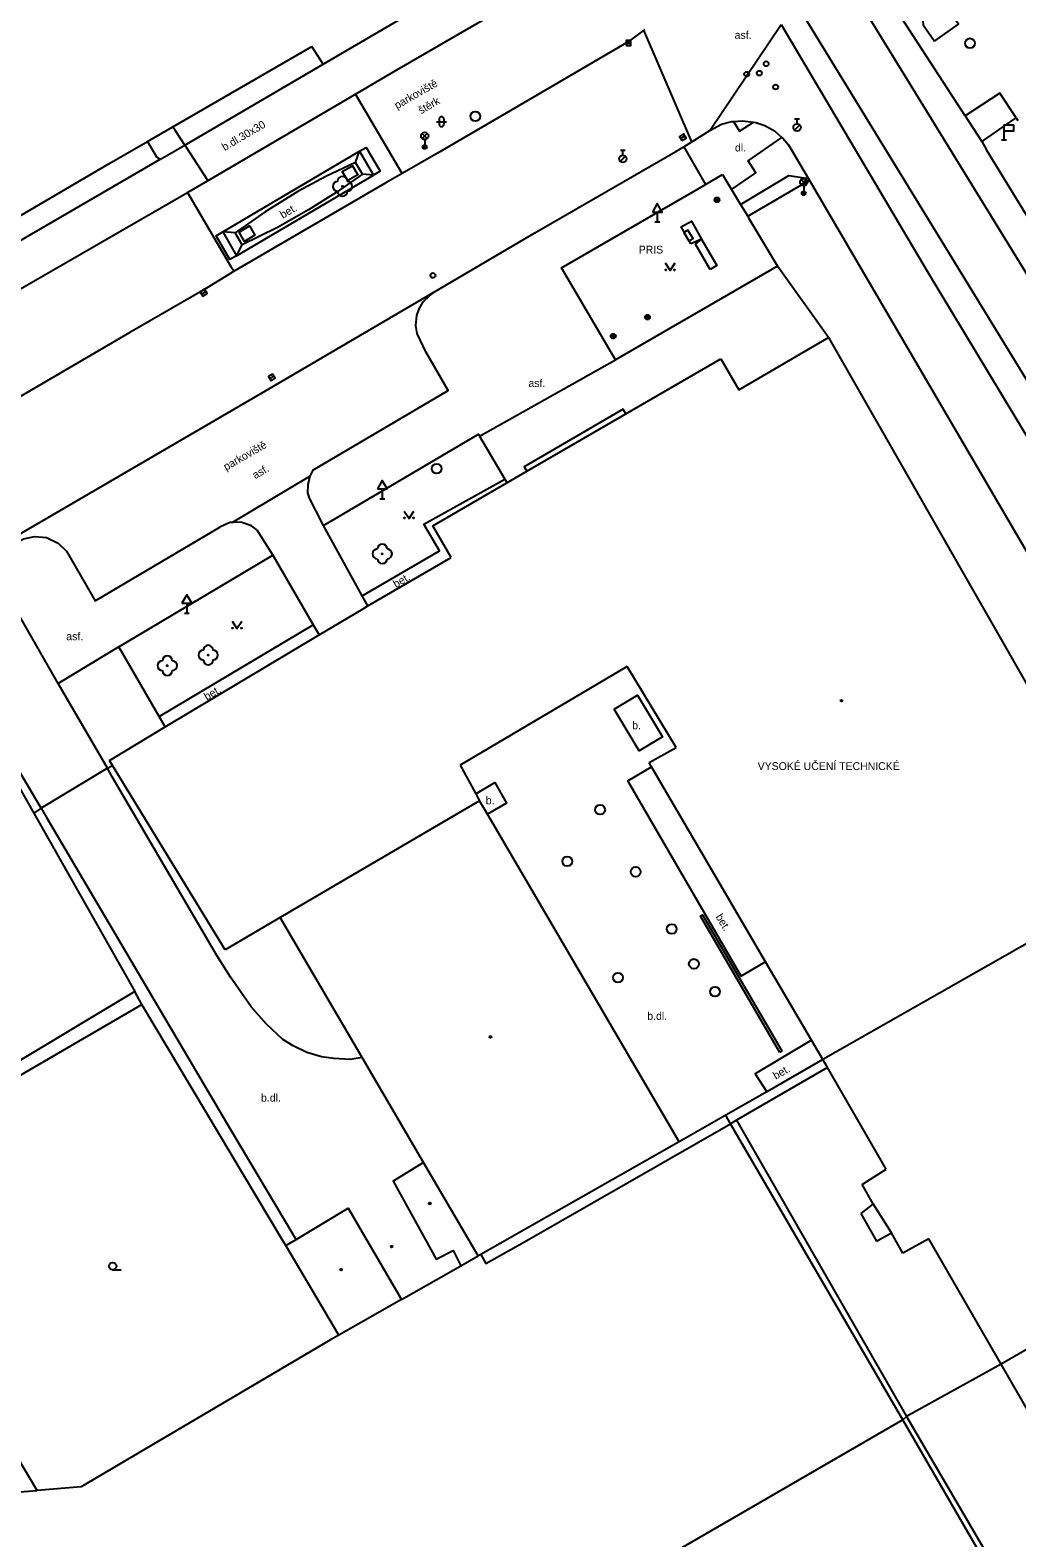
# Model space of a CAD drawing. Extents: x -599770 to -598493, y -1162076 to -1159209.
# Drawn here: x -599124.7 to -599074.3, y -1159515 to -1159438 of the extents above; entities that cross this region are included whole.
import ezdxf

# ---------------------------------------------------------------- set-up
doc = ezdxf.new("R2010")
doc.units = 0
doc.layers.add('Podklad', color=7, linetype='Continuous')

msp = doc.modelspace()

# ---------------------------------------------------------------- linework, layer by layer
at = {"layer": 'Podklad'}
for p, q in [((-599094.245, -1159438.68), (-599093.995, -1159438.68)), ((-599103.923, -1159442.698), (-599103.423, -1159442.698)), ((-599103.798, -1159442.573), (-599103.798, -1159442.823)), ((-599103.548, -1159442.573), (-599103.548, -1159442.823)), ((-599085.639, -1159443.126), (-599085.374, -1159442.861)), ((-599085.635, -1159442.552), (-599085.385, -1159442.552)), ((-599085.51, -1159442.802), (-599085.51, -1159442.552)), ((-599104.663, -1159443.56), (-599104.398, -1159443.295)), ((-599104.663, -1159443.295), (-599104.398, -1159443.56)), ((-599104.53, -1159443.615), (-599104.53, -1159443.99)), ((-599091.457, -1159443.555), (-599091.243, -1159443.425)), ((-599075.065, -1159443.62), (-599074.815, -1159443.62)), ((-599074.94, -1159443.17), (-599074.94, -1159443.62)), ((-599094.539, -1159444.726), (-599094.274, -1159444.461)), ((-599094.535, -1159444.152), (-599094.285, -1159444.152)), ((-599094.41, -1159444.402), (-599094.41, -1159444.152)), ((-599085.303, -1159445.92), (-599085.038, -1159445.655)), ((-599085.303, -1159445.655), (-599085.038, -1159445.92)), ((-599085.17, -1159445.975), (-599085.17, -1159446.35)), ((-599092.65, -1159447.311), (-599092.65, -1159447.82)), ((-599092.775, -1159447.82), (-599092.525, -1159447.82)), ((-599115.927, -1159451.495), (-599115.713, -1159451.365)), ((-599112.447, -1159455.825), (-599112.233, -1159455.695)), ((-599106.825, -1159461.96), (-599106.575, -1159461.96)), ((-599106.7, -1159461.451), (-599106.7, -1159461.96)), ((-599116.68, -1159467.291), (-599116.68, -1159467.8)), ((-599116.805, -1159467.8), (-599116.555, -1159467.8)), ((-599120.47, -1159501.337), (-599120.032, -1159501.337))]:
    msp.add_line(p, q, dxfattribs=at)
for points in [[(-599039.34, -1159506.49), (-599081.92, -1159437.24), (-599097.95, -1159410.38), (-599103.87, -1159400.3), (-599106.93, -1159394.94), (-599112.18, -1159386.13), (-599122.02, -1159369.06), (-599131.59, -1159352.73), (-599141.23, -1159336.24), (-599151.13, -1159319.11), (-599165.12, -1159295.05), (-599171.44, -1159284.11), (-599177.89, -1159272.64), (-599183.68, -1159262.09), (-599192.24, -1159246.86)], [(-599194.89, -1159248.28), (-599186.31, -1159263.55), (-599180.61, -1159273.94), (-599174.09, -1159285.5), (-599167.84, -1159296.37), (-599153.7, -1159320.73), (-599143.87, -1159337.58), (-599134.14, -1159354.17), (-599124.59, -1159370.66), (-599115.4, -1159386.56), (-599106.63, -1159401.44), (-599100.63, -1159411.8), (-599090.87, -1159427.91), (-599085.27, -1159437.13), (-599041.98, -1159507.82)], [(-599109.72, -1159439.76), (-599096.69, -1159432.14)], [(-599106.16, -1159440.17), (-599095.45, -1159433.96)], [(-599076.919, -1159442.396), (-599081.578, -1159435.231)], [(-599078.495, -1159438.582), (-599077.258, -1159437.72), (-599077.856, -1159436.898), (-599078.12, -1159436.786), (-599078.404, -1159436.756), (-599078.621, -1159436.774), (-599078.772, -1159436.84), (-599078.907, -1159436.966), (-599079.033, -1159437.172), (-599079.106, -1159437.406), (-599079.063, -1159437.75), (-599078.495, -1159438.582)], [(-599093.29, -1159437.99), (-599093.338, -1159438.026), (-599094.14, -1159438.62), (-599100.16, -1159442.14), (-599103.85, -1159444.29)], [(-599090.88, -1159443.73), (-599093.338, -1159438.026)], [(-599089.97, -1159443.15), (-599086.329, -1159437.731)], [(-599086.329, -1159437.731), (-599078.82, -1159450.42), (-599073.9, -1159458.57), (-599067.11, -1159469.527)], [(-599118.69, -1159443.71), (-599117.393, -1159442.96), (-599110.302, -1159438.861)], [(-599109.72, -1159439.76), (-599110.18, -1159439.05), (-599110.302, -1159438.861)], [(-599117.91, -1159444.55), (-599116.786, -1159443.892), (-599109.72, -1159439.76)], [(-599116.65, -1159446.31), (-599115.6, -1159445.7), (-599108.07, -1159441.29), (-599106.16, -1159440.17)], [(-599105.69, -1159445.35), (-599108.07, -1159441.29)], [(-599074.325, -1159442.504), (-599075.149, -1159441.239), (-599076.919, -1159442.396), (-599076.068, -1159443.706)], [(-599089.97, -1159443.15), (-599089.37, -1159442.83), (-599088.85, -1159442.69), (-599088.76, -1159442.68), (-599088.3, -1159442.65), (-599087.74, -1159442.72), (-599087.61, -1159442.74), (-599087.16, -1159442.9), (-599086.66, -1159443.17), (-599086.28, -1159443.5), (-599086.23, -1159443.54), (-599085.93, -1159443.89)], [(-599088.76, -1159442.68), (-599088.454, -1159443.179), (-599087.74, -1159442.72)], [(-599076.068, -1159443.706), (-599075.99, -1159443.652), (-599074.423, -1159442.572), (-599074.325, -1159442.504)], [(-599074.325, -1159442.504), (-599074.24, -1159442.63)], [(-599120.61, -1159444.82), (-599118.69, -1159443.71)], [(-599118.69, -1159443.71), (-599118.23, -1159444.5)], [(-599116.702, -1159444.021), (-599116.786, -1159443.892), (-599117.264, -1159443.158), (-599117.393, -1159442.96)], [(-599091.71, -1159444.22), (-599091.3, -1159443.98), (-599090.88, -1159443.73), (-599089.97, -1159443.15)], [(-599088.86, -1159446.16), (-599087.618, -1159445.318), (-599088.015, -1159444.693), (-599086.28, -1159443.5)], [(-599076.068, -1159443.706), (-599075.84, -1159444.13)], [(-599115.604, -1159445.698), (-599116.702, -1159444.021)], [(-599114.84, -1159448.33), (-599107.86, -1159444.21)], [(-599108.06, -1159444.78), (-599107.86, -1159444.21)], [(-599107.86, -1159444.21), (-599107.52, -1159444.02), (-599106.81, -1159445.23), (-599107.14, -1159445.43)], [(-599107.86, -1159444.21), (-599107.14, -1159445.43)], [(-599103.85, -1159444.29), (-599105.69, -1159445.35), (-599106.51, -1159445.82)], [(-599103.94, -1159451.34), (-599098.9, -1159448.37), (-599091.71, -1159444.22)], [(-599091.3, -1159443.98), (-599090.18, -1159445.9)], [(-599084.88, -1159445.69), (-599084.93, -1159445.6), (-599085.93, -1159443.89)], [(-599044.01, -1159496.09), (-599061.665, -1159467.27), (-599075.84, -1159444.13)], [(-599144.27, -1159459.85), (-599118.01, -1159444.59)], [(-599131.26, -1159451.04), (-599120.61, -1159444.82)], [(-599118.23, -1159444.5), (-599118.17, -1159444.55)], [(-599118.17, -1159444.55), (-599118.1, -1159444.58)], [(-599118.1, -1159444.58), (-599118.01, -1159444.59)], [(-599118.01, -1159444.59), (-599117.91, -1159444.55)], [(-599108.06, -1159444.78), (-599109.58, -1159445.49), (-599111.01, -1159446.26), (-599112.68, -1159447.3), (-599114.22, -1159448.38)], [(-599108.75, -1159445.25), (-599108.22, -1159444.96), (-599107.94, -1159445.42), (-599108.46, -1159445.71), (-599108.75, -1159445.25)], [(-599107.71, -1159445.38), (-599108.06, -1159444.78)], [(-599106.51, -1159445.82), (-599114.26, -1159450.34)], [(-599114.14, -1159449.55), (-599107.14, -1159445.43)], [(-599107.71, -1159445.38), (-599109.05, -1159446.32), (-599110.46, -1159447.2), (-599112.05, -1159448.1), (-599113.86, -1159448.99)], [(-599107.14, -1159445.43), (-599107.71, -1159445.38)], [(-599090.56, -1159446.12), (-599090.18, -1159445.9), (-599089.31, -1159445.4)], [(-599089.31, -1159445.4), (-599088.86, -1159446.16), (-599088.4, -1159446.92), (-599088.03, -1159447.53), (-599087.99, -1159447.6)], [(-599088.4, -1159446.92), (-599085.935, -1159445.445), (-599084.93, -1159445.6)], [(-599088.03, -1159447.53), (-599084.88, -1159445.69)], [(-599034.5, -1159531.73), (-599034.52, -1159531.7), (-599070.453, -1159470.331), (-599084.88, -1159445.69)], [(-599129.55, -1159453.79), (-599125.74, -1159451.56), (-599116.65, -1159446.31)], [(-599116.65, -1159446.31), (-599114.43, -1159450.1), (-599114.26, -1159450.34)], [(-599086.51, -1159450.07), (-599094.78, -1159454.86), (-599097.55, -1159450.16), (-599090.56, -1159446.12)], [(-599114.14, -1159449.55), (-599114.48, -1159449.74), (-599115.18, -1159448.53), (-599114.84, -1159448.33)], [(-599114.84, -1159448.33), (-599114.14, -1159449.55)], [(-599114.22, -1159448.38), (-599114.84, -1159448.33)], [(-599114.01, -1159448.34), (-599113.48, -1159448.02), (-599113.2, -1159448.5), (-599113.73, -1159448.81), (-599114.01, -1159448.34)], [(-599090.93, -1159448.94), (-599091.43, -1159448.07), (-599090.91, -1159447.77), (-599090.385, -1159448.69), (-599090.93, -1159448.94)], [(-599087.99, -1159447.6), (-599086.51, -1159450.07)], [(-599113.86, -1159448.99), (-599114.22, -1159448.38)], [(-599114.14, -1159449.55), (-599113.86, -1159448.99)], [(-599089.95, -1159450.25), (-599090.7, -1159448.96), (-599090.385, -1159448.69), (-599089.6, -1159450.05), (-599089.95, -1159450.25)], [(-599114.26, -1159450.34), (-599115.89, -1159451.33), (-599119.59, -1159453.47), (-599127.23, -1159457.93), (-599136.78, -1159463.47), (-599141.78, -1159466.43), (-599151.69, -1159472.19)], [(-599092.24, -1159449.915), (-599091.99, -1159450.29), (-599091.74, -1159449.915)], [(-599083.9, -1159453.72), (-599086.51, -1159450.07)], [(-599125.51, -1159463.94), (-599112.46, -1159456.32), (-599103.94, -1159451.34)], [(-599104.47, -1159454.45), (-599104.92, -1159453.52), (-599104.99, -1159453.1), (-599104.94, -1159452.6), (-599104.81, -1159452.25), (-599104.61, -1159451.9), (-599104.27, -1159451.57), (-599103.94, -1159451.34)], [(-599088.48, -1159456.39), (-599083.9, -1159453.72)], [(-599083.9, -1159453.72), (-599073.441, -1159471.999), (-599068.05, -1159481.42)], [(-599110.24, -1159460.49), (-599103.33, -1159456.42), (-599104.47, -1159454.45)], [(-599101.724, -1159458.756), (-599094.78, -1159454.86)], [(-599100.33, -1159461.14), (-599099.317, -1159460.554), (-599094.259, -1159457.624), (-599089.4, -1159454.81)], [(-599089.4, -1159454.81), (-599088.48, -1159456.39)], [(-599094.259, -1159457.624), (-599094.4, -1159457.38), (-599099.45, -1159460.33), (-599099.317, -1159460.554)], [(-599109.7, -1159463.32), (-599101.78, -1159458.66), (-599101.724, -1159458.756), (-599100.44, -1159460.95)], [(-599110.24, -1159460.49), (-599110.4, -1159460.81), (-599110.5, -1159461.24), (-599110.52, -1159461.66), (-599110.45, -1159461.85)], [(-599114.36, -1159463.17), (-599110.4, -1159460.81)], [(-599107.73, -1159466.91), (-599103.78, -1159464.61), (-599104.57, -1159463.25), (-599100.44, -1159460.95)], [(-599104.12, -1159463.34), (-599100.33, -1159461.14)], [(-599100.44, -1159460.95), (-599100.33, -1159461.14)], [(-599109.7, -1159463.32), (-599110.45, -1159461.85)], [(-599105.58, -1159462.585), (-599105.33, -1159462.96), (-599105.08, -1159462.585)], [(-599122.82, -1159464.63), (-599121.37, -1159467.17), (-599115, -1159463.41)], [(-599113.1, -1159463.54), (-599113.38, -1159463.34), (-599113.93, -1159463.15), (-599114.36, -1159463.17), (-599114.48, -1159463.17), (-599115, -1159463.41)], [(-599113.1, -1159463.54), (-599112.28, -1159464.84)], [(-599107.73, -1159466.91), (-599109.7, -1159463.32)], [(-599103.18, -1159464.95), (-599104.12, -1159463.34)], [(-599125.91, -1159466.75), (-599126.21, -1159466.01), (-599126.22, -1159465.44), (-599125.92, -1159464.7), (-599125.54, -1159464.3), (-599125.304, -1159464.164), (-599125.02, -1159464), (-599124.46, -1159463.88), (-599123.85, -1159463.94), (-599123.25, -1159464.22), (-599122.82, -1159464.63)], [(-599118.09, -1159473.07), (-599120.15, -1159469.51), (-599112.28, -1159464.84)], [(-599112.28, -1159464.84), (-599110.22, -1159468.4)], [(-599107.44, -1159467.43), (-599103.18, -1159464.95)], [(-599120.73, -1159475.71), (-599123.25, -1159471.39), (-599125.91, -1159466.75)], [(-599109.92, -1159468.91), (-599107.68, -1159467.57)], [(-599107.44, -1159467.43), (-599107.73, -1159466.91)], [(-599107.68, -1159467.57), (-599107.44, -1159467.43)], [(-599114.37, -1159468.215), (-599114.12, -1159468.59), (-599113.87, -1159468.215)], [(-599118.09, -1159473.07), (-599110.22, -1159468.4)], [(-599117.78, -1159473.61), (-599109.92, -1159468.91)], [(-599110.22, -1159468.4), (-599109.92, -1159468.91)], [(-599120.15, -1159469.51), (-599123.249, -1159471.39)], [(-599094.18, -1159470.53), (-599102.72, -1159475.56)], [(-599091.68, -1159474.66), (-599094.18, -1159470.53)], [(-599094.86, -1159472.7), (-599093.66, -1159471.98), (-599092.38, -1159474.11), (-599093.58, -1159474.83), (-599094.86, -1159472.7)], [(-599126.95, -1159473.73), (-599124.5, -1159478.01)], [(-599126.64, -1159473.54), (-599124.14, -1159477.74), (-599124.13, -1159477.75)], [(-599120.63, -1159475.32), (-599117.78, -1159473.61)], [(-599117.78, -1159473.61), (-599118.09, -1159473.07)], [(-599093.07, -1159475.42), (-599091.68, -1159474.66)], [(-599120.73, -1159475.71), (-599124.13, -1159477.75)], [(-599120.73, -1159475.71), (-599120.47, -1159475.58)], [(-599107.73, -1159490.5), (-599108.34, -1159490.59), (-599109.18, -1159490.55), (-599109.81, -1159490.46), (-599110.55, -1159490.23), (-599111.25, -1159489.9), (-599111.77, -1159489.58), (-599112.62, -1159488.79), (-599113.4, -1159487.9), (-599114.45, -1159486.39), (-599115.15, -1159485.29), (-599120.49, -1159476.15), (-599120.73, -1159475.71)], [(-599120.47, -1159475.58), (-599120.63, -1159475.32)], [(-599114.73, -1159484.99), (-599120.47, -1159475.58)], [(-599102.72, -1159475.56), (-599101.92, -1159477.03)], [(-599087.12, -1159485.6), (-599088.37, -1159486.33), (-599094.16, -1159476.36), (-599092.94, -1159475.64)], [(-599092.94, -1159475.64), (-599093.07, -1159475.42)], [(-599087.12, -1159485.6), (-599092.94, -1159475.64)], [(-599101.92, -1159477.03), (-599100.95, -1159476.45), (-599100.35, -1159477.5), (-599101.32, -1159478.07)], [(-599101.73, -1159477.38), (-599111.92, -1159483.34)], [(-599101.92, -1159477.03), (-599101.73, -1159477.38)], [(-599101.32, -1159478.07), (-599101.73, -1159477.38)], [(-599124.13, -1159477.75), (-599124.5, -1159478.01)], [(-599124.5, -1159478.01), (-599119.34, -1159487.12)], [(-599124.13, -1159477.75), (-599123.86, -1159478.2), (-599118.42, -1159487.45), (-599114.45, -1159494.17), (-599111.26, -1159499.51)], [(-599091.54, -1159494.8), (-599101.32, -1159478.07)], [(-599068.05, -1159481.42), (-599084.19, -1159490.6)], [(-599111.92, -1159483.34), (-599114.73, -1159484.99)], [(-599107.73, -1159490.5), (-599111.92, -1159483.34)], [(-599086.39, -1159490.23), (-599090.45, -1159483.27), (-599090.34, -1159483.2), (-599086.28, -1159490.16), (-599086.39, -1159490.23)], [(-599084.78, -1159489.6), (-599087.12, -1159485.6)], [(-599119.34, -1159487.12), (-599126.11, -1159491.19)], [(-599118.98, -1159487.78), (-599119.34, -1159487.12)], [(-599125.82, -1159491.77), (-599118.98, -1159487.78)], [(-599111.8, -1159499.82), (-599118.98, -1159487.78)], [(-599084.78, -1159489.6), (-599087.65, -1159491.32), (-599087.06, -1159492.24)], [(-599084.19, -1159490.6), (-599084.78, -1159489.6)], [(-599104.59, -1159495.86), (-599107.73, -1159490.5)], [(-599084.19, -1159490.6), (-599087.06, -1159492.24)], [(-599083.96, -1159491.01), (-599084.19, -1159490.6)], [(-599083.96, -1159491.01), (-599088.61, -1159493.7)], [(-599080.96, -1159496.2), (-599083.96, -1159491.01)], [(-599087.06, -1159492.24), (-599089.15, -1159493.44)], [(-599089.15, -1159493.44), (-599091.54, -1159494.8)], [(-599088.91, -1159493.88), (-599089.15, -1159493.44)], [(-599088.61, -1159493.7), (-599088.91, -1159493.88)], [(-599088.61, -1159493.7), (-599079.92, -1159508.82)], [(-599099.43, -1159499.9), (-599088.91, -1159493.88)], [(-599080.11, -1159508.99), (-599088.91, -1159493.88)], [(-599091.54, -1159494.8), (-599099.69, -1159499.43)], [(-599104.59, -1159495.86), (-599106.14, -1159496.8), (-599103.94, -1159500.8), (-599103.08, -1159500.35), (-599102.68, -1159501.13), (-599101.8, -1159500.63)], [(-599101.8, -1159500.63), (-599104.59, -1159495.86)], [(-599124.32, -1159512.61), (-599133.87, -1159496.59)], [(-599082.18, -1159496.98), (-599080.96, -1159496.2)], [(-599081.63, -1159497.96), (-599082.18, -1159496.98)], [(-599059.02, -1159496.89), (-599075.09, -1159506.15)], [(-599111.1, -1159499.78), (-599108.44, -1159498.19), (-599105.72, -1159502.86)], [(-599081.63, -1159497.96), (-599082.26, -1159498.46)], [(-599080.68, -1159499.44), (-599081.63, -1159497.96)], [(-599082.26, -1159498.46), (-599081.46, -1159499.87)], [(-599111.63, -1159500.1), (-599111.8, -1159499.82)], [(-599111.63, -1159500.1), (-599111.1, -1159499.78)], [(-599111.1, -1159499.78), (-599111.26, -1159499.51)], [(-599099.69, -1159499.43), (-599101.67, -1159500.56), (-599101.8, -1159500.63)], [(-599101.67, -1159500.56), (-599101.4, -1159501.02), (-599099.43, -1159499.9)], [(-599081.46, -1159499.87), (-599080.68, -1159499.44)], [(-599080.11, -1159500.48), (-599080.68, -1159499.44)], [(-599078.78, -1159499.76), (-599080.11, -1159500.48)], [(-599075.09, -1159506.15), (-599078.78, -1159499.76)], [(-599108.91, -1159504.67), (-599111.63, -1159500.1)], [(-599105.72, -1159502.86), (-599102.68, -1159501.13)], [(-599105.72, -1159502.86), (-599108.91, -1159504.67)], [(-599108.91, -1159504.67), (-599109.34, -1159504.92), (-599122.08, -1159512.42)], [(-599075.09, -1159506.15), (-599079.92, -1159508.82)], [(-599070.26, -1159514.52), (-599075.09, -1159506.15)], [(-599080.11, -1159508.99), (-599103.25, -1159522.39)], [(-599079.92, -1159508.82), (-599080.11, -1159508.99)], [(-599068.08, -1159529.76), (-599080.11, -1159508.99)], [(-599079.92, -1159508.82), (-599074.36, -1159518.34)], [(-599142.16, -1159513.99), (-599124.32, -1159512.61)], [(-599122.08, -1159512.42), (-599124.32, -1159512.61)]]:
    msp.add_lwpolyline(points, dxfattribs=at)
for points in [[(-599094.245, -1159438.805), (-599093.995, -1159438.805), (-599093.995, -1159438.555), (-599094.245, -1159438.555)], [(-599074.94, -1159443.17), (-599074.44, -1159443.17), (-599074.44, -1159442.87), (-599074.94, -1159442.87)], [(-599091.391, -1159443.662), (-599091.178, -1159443.531), (-599091.309, -1159443.318), (-599091.522, -1159443.449)], [(-599092.9, -1159447.311), (-599092.4, -1159447.311), (-599092.65, -1159446.878)], [(-599091.297, -1159448.362), (-599091.036, -1159448.788), (-599090.823, -1159448.658), (-599091.084, -1159448.232)], [(-599115.861, -1159451.602), (-599115.648, -1159451.471), (-599115.779, -1159451.258), (-599115.992, -1159451.389)], [(-599112.381, -1159455.932), (-599112.168, -1159455.801), (-599112.299, -1159455.588), (-599112.512, -1159455.719)], [(-599106.95, -1159461.451), (-599106.45, -1159461.451), (-599106.7, -1159461.018)], [(-599116.93, -1159467.291), (-599116.43, -1159467.291), (-599116.68, -1159466.858)]]:
    msp.add_lwpolyline(points, close=True, dxfattribs=at)
for centre, radius in [((-599076.68, -1159438.69), 0.25), ((-599087.09, -1159439.74), 0.125), ((-599088.08, -1159440.27), 0.125), ((-599087.44, -1159440.22), 0.125), ((-599086.6, -1159440.93), 0.125), ((-599101.94, -1159442.42), 0.25), ((-599085.51, -1159442.99), 0.188), ((-599104.53, -1159443.427), 0.188), ((-599104.53, -1159443.99), 0.1), ((-599104.53, -1159443.99), 0.0723), ((-599104.53, -1159443.99), 0.0438), ((-599094.41, -1159444.59), 0.188), ((-599108.73, -1159446), 0.025), ((-599085.17, -1159445.788), 0.188), ((-599089.6, -1159446.69), 0.125), ((-599089.6, -1159446.69), 0.1), ((-599089.6, -1159446.69), 0.075), ((-599089.6, -1159446.69), 0.05), ((-599089.6, -1159446.69), 0.025), ((-599085.17, -1159446.35), 0.1), ((-599085.17, -1159446.35), 0.0723), ((-599085.17, -1159446.35), 0.0438), ((-599104.11, -1159450.55), 0.125), ((-599092.215, -1159450.265), 0.025), ((-599091.765, -1159450.265), 0.025), ((-599093.15, -1159452.68), 0.125), ((-599093.15, -1159452.68), 0.1), ((-599093.15, -1159452.68), 0.075), ((-599093.15, -1159452.68), 0.05), ((-599093.15, -1159452.68), 0.025), ((-599094.9, -1159453.65), 0.125), ((-599094.9, -1159453.65), 0.1), ((-599094.9, -1159453.65), 0.075), ((-599094.9, -1159453.65), 0.05), ((-599094.9, -1159453.65), 0.025), ((-599103.92, -1159460.42), 0.25), ((-599105.555, -1159462.935), 0.025), ((-599105.105, -1159462.935), 0.025), ((-599106.7, -1159464.77), 0.025), ((-599114.345, -1159468.565), 0.025), ((-599113.895, -1159468.565), 0.025), ((-599117.68, -1159470.48), 0.025), ((-599115.59, -1159469.94), 0.025), ((-599083.24, -1159472.27), 0.045), ((-599083.24, -1159472.27), 0.0199), ((-599095.57, -1159477.84), 0.25), ((-599097.25, -1159480.47), 0.25), ((-599093.75, -1159481.01), 0.25), ((-599091.91, -1159483.93), 0.25), ((-599090.78, -1159485.71), 0.25), ((-599094.66, -1159486.41), 0.25), ((-599089.7, -1159487.13), 0.25), ((-599101.17, -1159489.44), 0.045), ((-599101.17, -1159489.44), 0.0199), ((-599104.27, -1159497.95), 0.045), ((-599104.27, -1159497.95), 0.0199), ((-599106.22, -1159500.15), 0.045), ((-599106.22, -1159500.15), 0.0199), ((-599120.47, -1159501.15), 0.188), ((-599108.8, -1159501.33), 0.045), ((-599108.8, -1159501.33), 0.0199)]:
    msp.add_circle(centre, radius, dxfattribs=at)
for centre, radius, start, end in [((-599103.673, -1159442.573), 0.125, 0, 180), ((-599103.673, -1159442.823), 0.125, 180, 0), ((-599108.98, -1159446), 0.25, 90, 270), ((-599108.73, -1159445.75), 0.25, 0, 180), ((-599108.48, -1159446), 0.25, 270, 90), ((-599108.73, -1159446.25), 0.25, 180, 0), ((-599106.7, -1159464.52), 0.25, 0, 180), ((-599106.95, -1159464.77), 0.25, 90, 270), ((-599106.7, -1159465.02), 0.25, 180, 0), ((-599106.45, -1159464.77), 0.25, 270, 90), ((-599115.84, -1159469.94), 0.25, 90, 270), ((-599115.59, -1159469.69), 0.25, 0, 180), ((-599115.34, -1159469.94), 0.25, 270, 90), ((-599117.93, -1159470.48), 0.25, 90, 270), ((-599117.68, -1159470.23), 0.25, 0, 180), ((-599117.43, -1159470.48), 0.25, 270, 90), ((-599115.59, -1159470.19), 0.25, 180, 0), ((-599117.68, -1159470.73), 0.25, 180, 0)]:
    msp.add_arc(centre, radius, start, end, dxfattribs=at)

# ---------------------------------------------------------------- texts
for s, p in [('asf.', (-599088.7, -1159438.47)), ('dl.', (-599088.68, -1159444.22)), ('PRIS', (-599093.6, -1159449.43)), ('asf.', (-599099.23, -1159456.25)), ('asf.', (-599122.84, -1159469.18)), ('b.', (-599093.93, -1159473.73)), ('VYSOKÉ UČENÍ TECHNICKÉ', (-599087.52, -1159475.81)), ('b.', (-599101.41, -1159477.56)), ('b.dl.', (-599093.16, -1159488.57)), ('b.dl.', (-599112.89, -1159492.75))]:
    msp.add_text(s, height=0.4, dxfattribs=at).set_placement(p)
for s, rotation, p in [('parkoviště', 30, (-599105.94, -1159442.07)), ('štěrk', 30, (-599104.72, -1159442.33)), ('b.dl.30x30', 30.25838, (-599114.75, -1159444.2)), ('bet.', 30.43, (-599111.78, -1159447.66)), ('parkoviště', 30, (-599114.67, -1159460.53)), ('asf.', 30, (-599113.19, -1159460.96)), ('bet.', 30.37, (-599106, -1159466.52)), ('bet.', 30.78, (-599115.66, -1159472.27)), ('bet.', 301.64, (-599089.69, -1159483.31)), ('bet.', 29.77, (-599086.6, -1159491.63))]:
    msp.add_text(s, height=0.4, rotation=rotation, dxfattribs=at).set_placement(p)

doc.saveas('drawing.dxf')
